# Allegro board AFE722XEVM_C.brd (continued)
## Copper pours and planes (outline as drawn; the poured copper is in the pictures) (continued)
N29999779 on TOP (solid shape): 99.44,44.04 100.2,44.04 100.2,42.77 98.76,42.77 98.73,42.8 98.42,42.8 98.42,44.04 98.17,44.3 97.54,44.3 97.54,45.01 98.48,45.01
N29999791 on TOP (solid shape): 95.12,47.85 95.38,47.6 96.01,47.6 96.01,46.89 95.07,46.89 94.08,47.88 93.4,47.88 93.37,47.9 93.37,49.1 95.12,49.1
N29999793 on TOP (solid shape): 96.01,44.3 95.38,44.3 95.12,44.04 95.12,42.8 93.37,42.8 93.37,44.02 94.08,44.02 95.07,45.01 96.01,45.01
N29999817 on TOP (solid shape): 110.9,44.17 111.58,44.17 111.61,44.15 111.61,42.95 109.86,42.95 109.86,44.2 109.6,44.45 108.97,44.45 108.97,45.16 109.91,45.16
N30111387 on TOP (solid shape): 129.54,79.12 127.76,79.12 127.76,79.76 130.17,79.76
N30111389 on TOP (solid shape): 132.97,80.01 131.57,80.01 131.14,80.44 131.14,80.49 131.93,80.49 132.13,80.7 132.97,80.7
N30111452 on TOP (solid shape): 128.02,82.17 129.03,82.17 129.92,81.28 129.92,81.15 124.28,81.15 124.28,82.68 125.48,82.68 127,84.2 128.02,84.2
N30525626 on TOP (solid shape): 111.66,32.36 110.95,32.36 109.96,31.37 109.02,31.37 109.02,32.08 109.65,32.08 109.91,32.33 109.91,33.58 111.66,33.58
N30527255 on TOP (solid shape): 111.61,48.03 110.9,48.03 109.91,47.04 108.97,47.04 108.97,47.75 109.6,47.75 109.86,48.01 109.86,49.25 111.61,49.25
N31236900 on BOTTOM (solid shape): 122.17,96.9 121.41,96.9 121.41,97.92 115.06,97.92 115.06,98.93 122.17,98.93
N31627077 on TOP (solid shape): 22.61,37.27 22.87,37.27 22.87,37.09 22.61,36.84 22.61,35.95 21.85,35.95 21.85,36.58 21.85,36.84 21.6,37.09 21.6,37.27 21.85,37.27 21.85,38.61 22.61,38.61
N31627077 on TOP (solid shape): 22.61,33.53 22.87,33.28 22.87,32.36 22.84,32.34 22.61,32.34 22.61,31.76 21.85,31.76 21.85,32.24 21.6,32.24 21.6,33.28 21.85,33.53 21.85,33.79 21.85,34.42 22.61,34.42
N31630401 on TOP (solid shape): 25.4,37.17 25.38,37.14 25.38,36.84 24.14,36.83 23.88,36.58 23.88,35.95 23.17,35.95 23.17,36.07 23.17,36.89 23.88,37.6 24.14,37.85 24.14,38.59 24.13,38.61 25.41,38.61
N31630404 on TOP (solid shape): 20.33,37.85 21.29,36.89 21.29,35.95 20.58,35.95 20.58,36.58 20.33,36.83 19.33,36.84 19.08,36.84 19.08,38.61 19.36,38.61 20.33,38.61

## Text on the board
BOTTOM: LAYER 6 (BOTTOM SIDE)
Board Geometry/Soldermask Bottom: SOLDERMASK BOTTOM
Ref Des/Silkscreen Bottom: SILKSCREEN BOTTOM
User.Comments: FID1 | J16 | C140 | C151 | U9 | U7 | C142 | C136 | FB6 | U18 | C120 | U4 | C150 | C139 | C149 | C148 | FB7 | C147 | C145 | C143 | C131 | FB15 | R139 | R160 | R159 | R141 | R137 | R138 | R158 | R136 | C53 | C50 | C80 | C82 | C84 | C78 | U16 | R9 | R1 | R6 | R11 | REVIEW MAN. DATASHEET - | SPECIAL MATERIAL REQUIRED | R48 | BOARD EDGE | J12 | C79 | C104 | C102 | C98 | C99 | C97 | FB5 | FB4 | C105 | R15 | R50 | R14 | C81 | C77 | R111 | C89 | R110 | C59 | R101 | C64 | C76 | C56 | C35 | R2 | R5 | C28 | C27 | C20 | C33 | C13 | C18 | C12 | C5 | C7 | C19 | C11 | C118 | C116 | C119 | C115 | C141 | C117 | C135 | C128 | FB12 | C414 | R119 | C121 | R131 | C187 | FB9 | C122 | R142 | C123 | C39 | C45 | C124 | C46 | C40 | C3 | C9 | U14 | C75 | R109 | R106 | C30 | C26 | C32 | C24 | C31 | C29 | C4 | C16 | C21 | C15 | Q1 | R145 | R143 | J15 | TEXAS INSTRUMENTS | AFE7225 EVM REV C
TOP: LAYER 1 (TOP SIDE)
Board Geometry/Soldermask Top: SOLDERMASK TOP
Ref Des/Silkscreen Top: 1 | +6V | GND | J12 | ON | LDO | DC/DC | J15 | IOUTB- | RFOUT | IOUTB | IOUTA | IOUTA- | VCM | RF LO IN | LOCK | VCTRL | CDC | CDC RST | CDC PDN | SILKSCREEN TOP | AFE7225EVM | REV C | DAC
L2_GND: LAYER 2
L3_PWR: LAYER 3
L4_PWR: LAYER 4
L5_GND: LAYER 5
DIMENSION: 45 X.150(2PL) | .450 | 5.600
DEVICE_TYPE_TOP: PASTEMASK TOP
USER_PART_NUM_TOP: PASTEMASK BOTTOM
User.9: 2.  FINISHED BOARD SHALL BE RoHS COMPLIANT.
User.10: 18  HOLES SIZE APPLIES AFTER PLATING.  TOLERANCE TO BE +.003/-.010. | 19. FILL ALL VIAS WITH NON-CONDUCTIVE FILL MATERIAL. | 20. FINISHED BOARDS MUST BE RoHS COMPLIANT AND SURVIVE A LEAD FREE ASSEMBLY, MAXIMUM REFLOW TEMPERATURE OF 260 DEGREE C (6 PASSES). | 18
User.16: FIGURE | SIZE | 6.0 | 10.0 | 13.0 | 36.0 | 38.0 | 40.0 | 45.0 | 55.0 | 62.0 | 67.0 | 68.0 | 120.0 | 140.0 | 125.0 | DRILL CHART: TOP to BOTTOM | ALL UNITS ARE IN MILS | TOLERANCE | +3.0/-3.0 | +0.0/-0.0 | +3.0/-0.0 | PLATED | NON-PLATED | QTY | 10 | 2344 | 50 | 4 | 5 | 8 | 12 | 40 | 2 | 1
